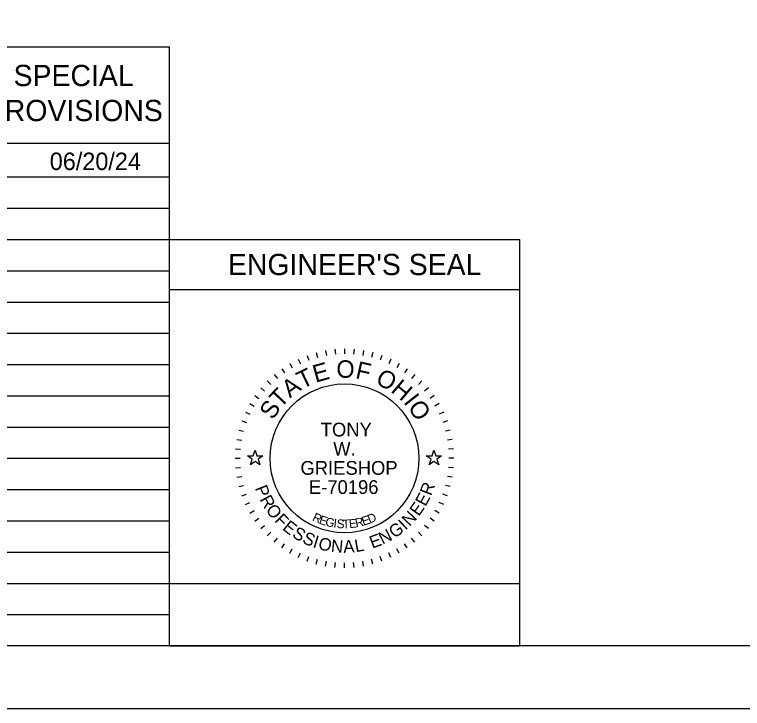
# Model space of a CAD drawing. Extents: x 0 to 34, y 0 to 22.
# Drawn here: x 22.36 to 28.18, y 0 to 5.55 of the extents above; entities that cross this region are included whole.
import ezdxf

# ---------------------------------------------------------------- set-up
doc = ezdxf.new("R2010")
doc.units = 0
for name, color, linetype in [('Default', 7, 'Continuous'), ('SH_Border', 7, 'Continuous'), ('SH_Cut_Line', 7, 'Continuous'), ('SH_Data', 7, 'Continuous'), ('SH_Text', 7, 'Continuous')]:
    doc.layers.add(name, color=color, linetype=linetype)

msp = doc.modelspace()

# ---------------------------------------------------------------- linework, layer by layer
at = {"layer": 'Default'}
for points in [[(24.2236, 2.02), (24.2705, 2.02), (24.285, 2.0645), (24.2995, 2.02), (24.3464, 2.02), (24.3085, 1.9924), (24.323, 1.9478), (24.285, 1.9754), (24.247, 1.9478), (24.2615, 1.9924)], [(25.6536, 2.02), (25.7005, 2.02), (25.715, 2.0645), (25.7295, 2.02), (25.7764, 2.02), (25.7385, 1.9924), (25.753, 1.9478), (25.715, 1.9754), (25.677, 1.9478), (25.6915, 1.9924)]]:
    msp.add_lwpolyline(points, close=True, dxfattribs=at)
at = {"layer": 'SH_Border'}
msp.add_lwpolyline([(1.5, 21.5), (33.5, 21.5), (33.5, 0.5), (1.5, 0.5)], close=True, dxfattribs=at)
at = {"layer": 'SH_Cut_Line'}
msp.add_lwpolyline([(0, 0), (34, 0), (34, 22), (0, 22)], close=True, dxfattribs=at)
at = {"layer": 'SH_Data'}
for p, q in [((10.15, 5.2917), (23.6, 5.2917)), ((23.6, 0.5), (23.6, 5.2917)), ((10.15, 4.5209), (23.6, 4.5209)), ((10.15, 4.25), (23.6, 4.25)), ((10.15, 4), (23.6, 4)), ((10.15, 3.75), (23.6, 3.75)), ((23.6, 0.5), (23.6, 3.75)), ((23.6, 3.75), (26.4, 3.75)), ((26.4, 3.75), (26.4, 0.5)), ((10.15, 3.5), (23.6, 3.5)), ((23.6, 3.35), (26.4, 3.35)), ((10.15, 3.25), (23.6, 3.25)), ((10.15, 3), (23.6, 3)), ((24.8481, 2.8617), (24.855, 2.8223)), ((24.9237, 2.8717), (24.9272, 2.8318)), ((25, 2.875), (25, 2.835)), ((25.0763, 2.8717), (25.0728, 2.8318)), ((25.1519, 2.8617), (25.145, 2.8223)), ((24.7007, 2.8222), (24.7144, 2.7846)), ((24.7735, 2.8452), (24.7839, 2.8065)), ((25.2265, 2.8452), (25.2161, 2.8065)), ((25.2993, 2.8222), (25.2856, 2.7846)), ((10.15, 2.75), (23.6, 2.75)), ((24.5625, 2.7578), (24.5825, 2.7231)), ((24.6302, 2.793), (24.6471, 2.7568)), ((25.3698, 2.793), (25.3529, 2.7568)), ((25.4375, 2.7578), (25.4175, 2.7231)), ((24.4981, 2.7168), (24.5211, 2.684)), ((25.5019, 2.7168), (25.4789, 2.684)), ((24.3813, 2.6187), (24.4096, 2.5904)), ((24.4376, 2.6703), (24.4633, 2.6396)), ((25.5624, 2.6703), (25.5367, 2.6396)), ((25.6187, 2.6187), (25.5904, 2.5904)), ((24.3297, 2.5624), (24.3604, 2.5367)), ((25.6703, 2.5624), (25.6396, 2.5367)), ((10.15, 2.5), (23.6, 2.5)), ((24.2832, 2.5019), (24.316, 2.4789)), ((25.7168, 2.5019), (25.684, 2.4789)), ((24.2422, 2.4375), (24.2769, 2.4175)), ((25.7578, 2.4375), (25.7231, 2.4175)), ((24.207, 2.3698), (24.2432, 2.3529)), ((25.793, 2.3698), (25.7568, 2.3529)), ((24.1778, 2.2993), (24.2154, 2.2856)), ((25.8222, 2.2993), (25.7846, 2.2856)), ((10.15, 2.25), (23.6, 2.25)), ((24.1548, 2.2265), (24.1935, 2.2161)), ((25.8452, 2.2265), (25.8065, 2.2161)), ((24.1383, 2.1519), (24.1777, 2.145)), ((25.8617, 2.1519), (25.8223, 2.145)), ((24.1283, 2.0763), (24.1682, 2.0728)), ((25.8717, 2.0763), (25.8318, 2.0728)), ((10.15, 2), (23.6, 2)), ((24.125, 2), (24.165, 2)), ((25.875, 2), (25.835, 2)), ((24.1283, 1.9237), (24.1682, 1.9272)), ((25.8717, 1.9237), (25.8318, 1.9272)), ((24.1383, 1.8481), (24.1777, 1.855)), ((25.8617, 1.8481), (25.8223, 1.855)), ((10.15, 1.75), (23.6, 1.75)), ((24.1548, 1.7735), (24.1935, 1.7839)), ((25.8452, 1.7735), (25.8065, 1.7839)), ((24.1778, 1.7007), (24.2154, 1.7144)), ((25.8222, 1.7007), (25.7846, 1.7144)), ((24.207, 1.6302), (24.2432, 1.6471)), ((25.793, 1.6302), (25.7568, 1.6471)), ((24.2422, 1.5625), (24.2769, 1.5825)), ((25.7578, 1.5625), (25.7231, 1.5825)), ((24.2832, 1.4981), (24.316, 1.5211)), ((25.7168, 1.4981), (25.684, 1.5211)), ((10.15, 1.5), (23.6, 1.5)), ((24.3297, 1.4376), (24.3604, 1.4633)), ((25.6703, 1.4376), (25.6396, 1.4633)), ((24.3813, 1.3813), (24.4096, 1.4096)), ((25.6187, 1.3813), (25.5904, 1.4096)), ((24.4376, 1.3297), (24.4633, 1.3604)), ((25.5624, 1.3297), (25.5367, 1.3604)), ((24.4981, 1.2832), (24.5211, 1.316)), ((25.5019, 1.2832), (25.4789, 1.316)), ((10.15, 1.25), (23.6, 1.25)), ((24.5625, 1.2422), (24.5825, 1.2769)), ((24.6302, 1.207), (24.6471, 1.2432)), ((25.3698, 1.207), (25.3529, 1.2432)), ((25.4375, 1.2422), (25.4175, 1.2769)), ((24.7007, 1.1778), (24.7144, 1.2154)), ((24.7735, 1.1548), (24.7839, 1.1935)), ((24.8481, 1.1383), (24.855, 1.1777)), ((24.9237, 1.1283), (24.9272, 1.1682)), ((25, 1.125), (25, 1.165)), ((25.0763, 1.1283), (25.0728, 1.1682)), ((25.1519, 1.1383), (25.145, 1.1777)), ((25.2265, 1.1548), (25.2161, 1.1935)), ((25.2993, 1.1778), (25.2856, 1.2154)), ((10.15, 1), (23.6, 1)), ((10.15, 0.75), (23.6, 0.75)), ((23.6, 0.5), (26.4, 0.5)), ((23.6, 0.5), (26.4, 0.5))]:
    msp.add_line(p, q, dxfattribs=at)
msp.add_lwpolyline([(23.6, 0.5), (23.6, 1), (26.4, 1), (26.4, 0.5)], close=True, dxfattribs=at)
msp.add_circle((25, 2), 0.595, dxfattribs=at)

# ---------------------------------------------------------------- texts
for s, height, p in [("ENGINEER'S SEAL", 0.17, (24.0676, 3.465)), ('TONY', 0.11, (24.8096, 2.1749)), ('W.', 0.11, (24.9095, 2.0216)), ('GRIESHOP', 0.11, (24.6477, 1.8684)), ('E-70196', 0.11, (24.7154, 1.7151))]:
    msp.add_text(s, height=height, dxfattribs=at).set_placement(p)
for s, height, rotation, p in [('E', 0.14, 15.75706, (24.7684, 2.6038)), ('O', 0.14, 359.78119, (24.9347, 2.6443)), ('F', 0.14, 347.43619, (25.0811, 2.6417)), ('T', 0.14, 25.71674, (24.6616, 2.5518)), ('O', 0.14, 332.25863, (25.2398, 2.6015)), ('A', 0.14, 36.47472, (24.5634, 2.4781)), ('H', 0.14, 319.91363, (25.3632, 2.5361)), ('T', 0.14, 46.4344, (24.4883, 2.3964)), ('I', 0.14, 308.36695, (25.4665, 2.4483)), ('S', 0.14, 57.19238, (24.4281, 2.3014)), ('O', 0.14, 303.14906, (25.5021, 2.4089)), ('R', 0.1, 69.23216, (25.6919, 1.6954)), ('P', 0.1, 291.49398, (24.2823, 1.7621)), ('R', 0.1, 298.73106, (24.319, 1.6717)), ('E', 0.1, 61.99508, (25.6476, 1.6098)), ('E', 0.1, 54.75801, (25.5933, 1.5314)), ('O', 0.1, 306.46664, (24.3655, 1.5883)), ('N', 0.1, 47.02243, (25.5202, 1.4508)), ('F', 0.1, 314.7068, (24.4343, 1.4983)), ('R', 0.07, 334.48695, (24.7375, 1.5051)), ('E', 0.07, 341.03996, (24.7906, 1.4801)), ('G', 0.07, 347.47515, (24.8414, 1.4618)), ('I', 0.07, 353.78581, (24.9091, 1.4468)), ('E', 0.07, 6.01169, (25.0389, 1.4412)), ('R', 0.07, 11.91844, (25.0925, 1.4474)), ('E', 0.07, 17.68363, (25.1498, 1.4602)), ('D', 0.07, 23.30524, (25.201, 1.477)), ('E', 0.1, 321.43929, (24.4978, 1.4348)), ('S', 0.07, 356.89262, (24.9358, 1.4429)), ('T', 0.07, 3.00609, (24.9857, 1.4387)), ('G', 0.1, 35.04687, (25.3981, 1.357)), ('I', 0.1, 43.28703, (25.4868, 1.4214)), ('S', 0.1, 328.67637, (24.5743, 1.3752)), ('S', 0.1, 335.91345, (24.6564, 1.3266)), ('E', 0.1, 20.07421, (25.2212, 1.277)), ('N', 0.1, 27.31129, (25.3045, 1.3075)), ('I', 0.1, 343.15053, (24.7406, 1.2897)), ('O', 0.1, 346.88592, (24.7839, 1.2751)), ('N', 0.1, 355.12608, (24.8888, 1.2517)), ('A', 0.1, 2.86166, (24.9923, 1.2437)), ('L', 0.1, 10.09874, (25.0894, 1.249))]:
    msp.add_text(s, height=height, rotation=rotation, dxfattribs=at).set_placement(p)
at = {"layer": 'SH_Text'}
for s, height, p in [('SPECIAL', 0.17, (22.3542, 4.9763)), ('PROVISIONS', 0.17, (22.1323, 4.6963)), ('06/20/24', 0.14, (22.6435, 4.305))]:
    msp.add_text(s, height=height, dxfattribs=at).set_placement(p)

doc.saveas('drawing.dxf')
